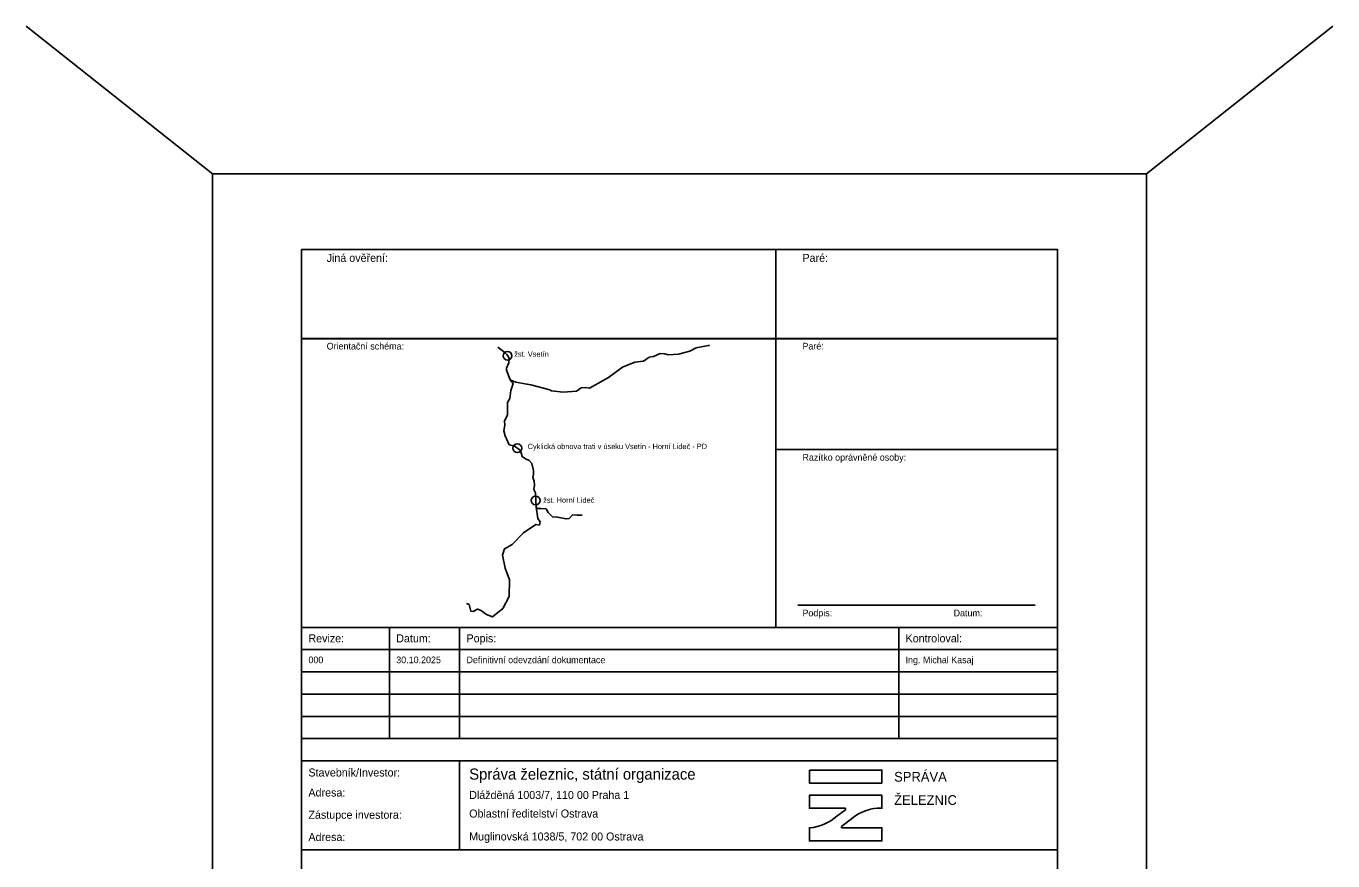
# Model space of a CAD drawing. Extents: x 366 to 2015, y -665 to 172.
# Drawn here: x 882.5 to 1176.4, y -16 to 171.8 of the extents above; entities that cross this region are included whole.
import ezdxf

# ---------------------------------------------------------------- set-up
doc = ezdxf.new("R2010")
doc.units = 0
for name, color, linetype in [('-zzz_temp', 7, 'Continuous'), ('Default', 7, 'Continuous'), ('Hranice státu', 7, 'Continuous'), ('Lidecko', 7, 'Continuous'), ('Rozpiska_Logo', 7, 'Continuous'), ('Rozpiska_pola_3', 7, 'Continuous'), ('Rozpiska_pole_1', 7, 'Continuous'), ('Rozpiska_pole_2', 7, 'Continuous'), ('Rozpiska_pole_4', 7, 'Continuous'), ('Rozpiska_pole_5', 7, 'Continuous'), ('Rozpiska_pole_6', 7, 'Continuous'), ('Rozpiska_pole_8', 7, 'Continuous')]:
    doc.layers.add(name, color=color, linetype=linetype)

msp = doc.modelspace()

# ---------------------------------------------------------------- linework, layer by layer
at = {"layer": '-zzz_temp'}
for p, q in [((882.48, 171.77), (924.42, 138.55)), ((1134.42, 138.55), (1176.36, 171.77))]:
    msp.add_line(p, q, dxfattribs=at)
msp.add_lwpolyline([(924.42, -158.45), (1134.42, -158.45), (1134.42, 138.55), (924.42, 138.55)], close=True, dxfattribs=at)
at = {"layer": 'Default'}
msp.add_line((1051.07, 36.55), (1051.07, 101.55), dxfattribs=at)
at = {"layer": 'Hranice státu'}
for points in [[(991.33, 92.2), (992.6, 91.72), (995.11, 91.27), (995.99, 91.08), (1000.25, 90.01), (1000.66, 89.77), (1003.28, 89.45), (1006.23, 89.7), (1007.28, 90.4), (1008.2, 90.5), (1009.18, 90.37), (1012.29, 92.06), (1013.45, 92.74), (1016.59, 95.09), (1019.35, 96.19), (1021.35, 96.44), (1022.6, 97.31), (1023.58, 97.46), (1025.06, 98.12), (1026.09, 98.08), (1026.89, 97.83), (1028.01, 97.92), (1029.19, 97.97), (1031.77, 98.67), (1033.18, 99.41), (1035.94, 99.96), (1036.2, 99.94)], [(991.33, 92.2), (990.52, 94.42), (990.53, 94.83), (991.03, 96.07), (991.13, 96.94), (990.93, 97.39), (990.58, 97.9), (990.24, 98.29), (988.56, 99.56)], [(990.75, 84.37), (990.72, 87.13), (991.29, 88.06), (991.47, 89.84), (991.98, 91.42), (991.33, 92.2)], [(996.73, 69.43), (996.4, 70.27), (996.6, 71), (996.61, 71.84), (996.21, 73.39), (995.61, 74.12), (994.81, 74.49), (994.01, 74.95), (993.66, 76.35), (992.23, 77.35), (991.13, 77.62), (990.22, 79.65), (989.91, 80.76), (990.15, 82.01), (990.06, 82.96), (990.75, 84.37)], [(997.16, 63.57), (997, 66.82), (996.65, 67.59), (996.78, 68.56), (996.73, 69.43)], [(981.51, 41.9), (982.1, 41.7), (982.47, 40.22), (983.02, 40.15), (984.01, 40.66), (984.63, 40.45), (986.04, 39.45), (987.39, 38.95), (989.71, 40.82), (991.11, 43.47), (991.18, 47.23), (990.21, 49.85), (989.61, 52.79), (990.1, 54.23), (991.77, 55.18), (994.31, 57.84), (997.09, 59.66), (997.93, 59.57), (998.09, 60.28), (997.58, 61.01), (997.16, 63.57)], [(1007.56, 61.76), (1006.38, 61.8), (1005.32, 61.84), (1004.64, 61.06), (1003.93, 60.96), (1002, 61.35), (1000.86, 61.44), (999.9, 62.4), (999.43, 63.19), (998.27, 63.27), (997.35, 63.3), (997.16, 63.57)]]:
    msp.add_lwpolyline(points, dxfattribs=at)
at = {"layer": 'Lidecko'}
for centre in [(990.75, 97.65), (992.95, 76.85), (997.08, 65.08)]:
    msp.add_circle(centre, 0.985, dxfattribs=at)
at = {"layer": 'Rozpiska_Logo'}
for p, q in [((1064.82, -5.92), (1066.76, -4.46)), ((1066.76, -4.46), (1066.76, -4.11)), ((1068.45, -6.19), (1065.84, -8.21)), ((1065.84, -8.21), (1065.84, -8.52))]:
    msp.add_line(p, q, dxfattribs=at)
msp.add_lwpolyline([(1058.64, 4.46), (1074.94, 4.46), (1074.94, 1.53), (1058.64, 1.53)], close=True, dxfattribs=at)
for points in [[(1066.76, -4.11), (1058.64, -4.11), (1058.64, -1.18), (1074.94, -1.18), (1074.94, -4.11), (1073.86, -4.11)], [(1065.84, -8.52), (1074.94, -8.52), (1074.94, -11.45), (1058.64, -11.45), (1058.64, -8.52), (1058.7, -8.52)]]:
    msp.add_lwpolyline(points, dxfattribs=at)
for centre, radius, start, end in [((1074.6, -14.13), 10.04, 94.2142, 127.7808), ((1057.86, 1.97), 10.52, 274.6014, 311.4254)]:
    msp.add_arc(centre, radius, start, end, dxfattribs=at)
at = {"layer": 'Rozpiska_pola_3'}
msp.add_line((1056.07, 41.55), (1109.42, 41.55), dxfattribs=at)
at = {"layer": 'Rozpiska_pole_1'}
msp.add_lwpolyline([(944.42, 121.55), (1114.42, 121.55), (1114.42, -143.45), (944.42, -143.45)], close=True, dxfattribs=at)
at = {"layer": 'Rozpiska_pole_2'}
for points in [[(944.42, 101.55), (1051.07, 101.55), (1051.07, 36.55), (944.42, 36.55)], [(1051.07, 101.55), (1114.42, 101.55), (1114.42, 76.55), (1051.07, 76.55)], [(1114.42, 76.55), (1051.07, 76.55), (1051.07, 36.55), (1114.42, 36.55)]]:
    msp.add_lwpolyline(points, close=True, dxfattribs=at)
at = {"layer": 'Rozpiska_pole_4'}
for p, q in [((964.17, 11.55), (964.17, 36.55)), ((979.97, 11.55), (979.97, 36.55)), ((1078.72, 11.55), (1078.72, 36.55)), ((944.42, 31.55), (1114.42, 31.55)), ((944.42, 26.55), (1114.42, 26.55)), ((944.42, 21.55), (1114.42, 21.55)), ((944.42, 16.55), (1114.42, 16.55))]:
    msp.add_line(p, q, dxfattribs=at)
msp.add_lwpolyline([(944.42, 36.55), (1114.42, 36.55), (1114.42, 11.55), (944.42, 11.55)], close=True, dxfattribs=at)
at = {"layer": 'Rozpiska_pole_5'}
msp.add_line((979.97, -13.45), (979.97, 6.55), dxfattribs=at)
msp.add_lwpolyline([(944.42, 6.55), (1114.42, 6.55), (1114.42, -13.45), (944.42, -13.45)], close=True, dxfattribs=at)
at = {"layer": 'Rozpiska_pole_8'}
for points in [[(944.42, 121.55), (1051.07, 121.55), (1051.07, 101.43), (944.42, 101.43)], [(1051.07, 121.55), (1114.42, 121.55), (1114.42, 101.43), (1051.07, 101.43)]]:
    msp.add_lwpolyline(points, close=True, dxfattribs=at)

# ---------------------------------------------------------------- texts
at = {"layer": 'Lidecko'}
for s, p in [('žst. Vsetín', (992.27, 97.42)), ('Cyklická obnova trati v úseku Vsetín - Horní Lideč - PD', (995.27, 76.65)), ('žst. Horní Lideč', (998.76, 64.57))]:
    msp.add_text(s, height=1.2, dxfattribs=at).set_placement(p)
at = {"layer": 'Rozpiska_pola_3'}
for s, height, p in [('Paré:', 1.8, (1057.07, 118.75)), ('Paré:', 1.5, (1057.07, 99.05)), ('Razítko oprávněné osoby:', 1.5, (1057.07, 74.05)), ('Podpis:', 1.5, (1057.07, 39.05)), ('Datum:', 1.5, (1091.07, 39.05))]:
    msp.add_text(s, height=height, dxfattribs=at).set_placement(p)
at = {"layer": 'Rozpiska_pole_2'}
for s, height, p in [('Jiná ověření:', 1.8, (950.07, 118.75)), ('Orientační schéma:', 1.5, (950.07, 99.05))]:
    msp.add_text(s, height=height, dxfattribs=at).set_placement(p)
at = {"layer": 'Rozpiska_pole_4'}
for s, height, p in [('Revize:', 1.8, (945.97, 33.2)), ('Datum:', 1.8, (965.72, 33.2)), ('Popis:', 1.8, (981.52, 33.2)), ('Kontroloval:', 1.8, (1080.27, 33.2)), ('000', 1.5, (945.97, 28.5)), ('30.10.2025', 1.5, (965.72, 28.5)), ('Definitivní odevzdání dokumentace', 1.5, (981.52, 28.5)), ('Ing. Michal Kasaj', 1.5, (1080.27, 28.5))]:
    msp.add_text(s, height=height, dxfattribs=at).set_placement(p)
at = {"layer": 'Rozpiska_pole_5'}
for s, height, p in [('Stavebník/Investor:', 1.8, (945.97, 3.02)), ('Správa železnic, státní organizace', 2.5, (982.12, 2.32)), ('Adresa:', 1.8, (945.97, -1.48)), ('Zástupce investora:', 1.8, (945.97, -6.48)), ('Adresa:', 1.8, (945.97, -11.48))]:
    msp.add_text(s, height=height, dxfattribs=at).set_placement(p)
at = {"layer": 'Rozpiska_pole_6'}
for s, height, p in [('SPRÁVA', 2.183, (1077.69, 1.87)), ('Dlážděná 1003/7, 110 00 Praha 1', 1.8, (982.12, -2.03)), ('ŽELEZNIC', 2.183, (1077.69, -3.36)), ('Oblastní ředitelství Ostrava', 1.8, (982.12, -6.21)), ('Muglinovská 1038/5, 702 00 Ostrava', 1.8, (982.12, -11.37))]:
    msp.add_text(s, height=height, dxfattribs=at).set_placement(p)

doc.saveas('drawing.dxf')
